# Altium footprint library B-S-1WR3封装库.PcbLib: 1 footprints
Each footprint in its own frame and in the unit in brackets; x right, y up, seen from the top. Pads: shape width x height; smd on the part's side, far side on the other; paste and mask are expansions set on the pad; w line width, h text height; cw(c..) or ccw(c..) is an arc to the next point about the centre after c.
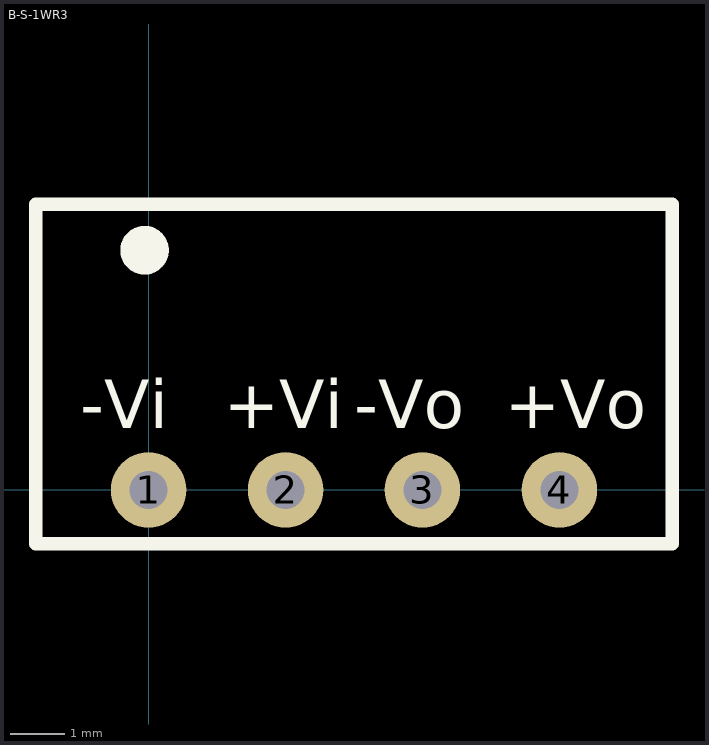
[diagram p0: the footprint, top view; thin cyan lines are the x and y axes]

## B-S-1WR3 [mm]
pads (4):
  round 1.4 hole 0.7: 1(0,0) 2(2.54,0) 3(5.08,0) 4(7.62,0)
Top Overlay:
  circle w0.5: c-0.073,4.445 r0.2
  lines w0.254: -2.09,-1 -2.09,5.3 9.71,5.3 9.71,-1 -2.09,-1
  text "+Vo" at 6.604,1.143 h0.9
  text "-Vo" at 3.81,1.143 h0.9
  text "+Vi" at 1.397,1.143 h0.9
  text "-Vi" at -1.27,1.143 h0.9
